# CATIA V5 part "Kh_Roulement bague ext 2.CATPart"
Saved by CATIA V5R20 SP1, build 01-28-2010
Part number: Roulement bague ext 2
Bounding box of the stored display mesh (mm): x -20 to 20, y -20 to 20, z -8 to 4
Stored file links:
  G:\Khaled_CFAO_2011\SIL\SIL_GR1\tmerino\Khaled\CAD_Thinkmotion\Kh_Roulement bague ext 2.CATPart
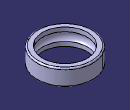
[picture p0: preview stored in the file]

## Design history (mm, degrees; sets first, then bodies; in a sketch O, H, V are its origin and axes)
Body1 (main body)
  Sketch1 on yz-plane, origin (0, 0, 0), H (0, 1, 0), V (0, 0, 1)
    line L1 (-20, -8) -> (-20, 4)
    line L2 (-20, 4) -> (-16, 4)
    line L3 (-20, -8) -> (-16, -8)
    line L4 (-16, 4) -> (-16, 1)
    line L5 (-16, -8) -> (-16, -5)
    arc A1 centre (-14.25, -2) radius 3.4731 from (-16, 1) to (-16, -5) ccw
    length L2 = 4
    length L3 = 4
    length L1 = 12
    length L4 = 3
    length L5 = 3
    distance L4 V = 16
    vertical: L1 V, L4 V, L5 V
    horizontal: L2 H, L3 H
  Shaft1: profile Sketch1, axis Sketch1.V, angle 360
  Fillet1: radius 1, on edge [face of Shaft1 from Sketch1.L1 | face of Shaft1 from Sketch1.L2]
  Fillet2: radius 1, on edge [face of Shaft1 from Sketch1.L3 | face of Shaft1 from Sketch1.L1]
